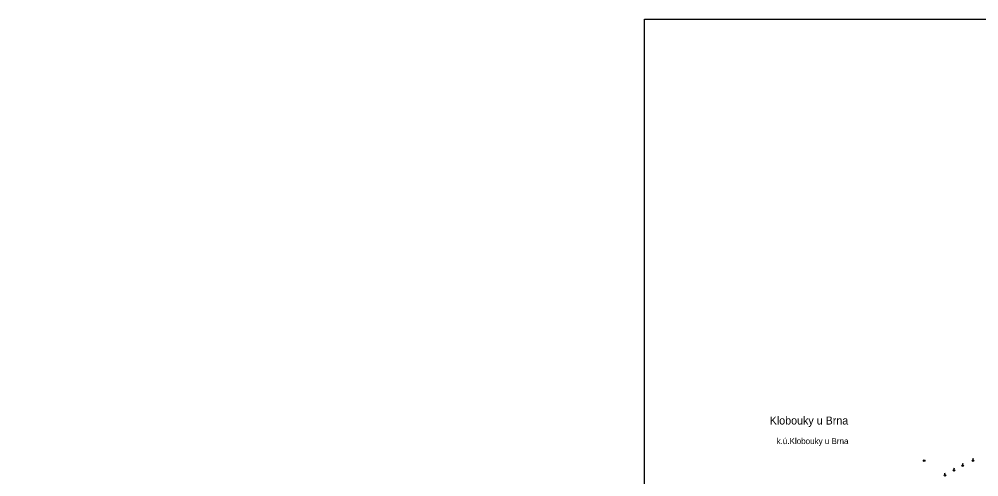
# Model space of a CAD drawing. Extents: x -582188 to -561562, y -1187250 to -1183500.
# Drawn here: x -582187.5 to -581707.9, y -1186228.8 to -1186000 of the extents above; entities that cross this region are included whole.
import ezdxf

# ---------------------------------------------------------------- set-up
doc = ezdxf.new("R2010")
doc.units = 0
for name, color, linetype in [('MAP_ZN_BP', 7, 'Continuous'), ('NÁZEV_K_Ú', 7, 'Continuous'), ('NÁZVY_SÍDEL_JEDNOTKY', 7, 'Continuous'), ('RÁMY_ML', 7, 'Continuous'), ('ZN_BP', 7, 'Continuous')]:
    doc.layers.add(name, color=color, linetype=linetype)

msp = doc.modelspace()

# ---------------------------------------------------------------- linework, layer by layer
at = {"layer": 'MAP_ZN_BP'}
for radius in [0.375, 0.0005]:
    msp.add_circle((-581735.24, -1186220.761), radius, dxfattribs=at)
at = {"layer": 'RÁMY_ML'}
msp.add_lwpolyline([(-581875, -1186000), (-581562.5, -1186000), (-581562.5, -1186250), (-581562.5, -1186500), (-581875, -1186500), (-582187.5, -1186500), (-582187.5, -1186250), (-581875, -1186250), (-581875, -1186000)], dxfattribs=at)
at = {"layer": 'ZN_BP'}
for p, q in [((-581711.095, -1186220.984), (-581710.566, -1186220.456)), ((-581710.566, -1186220.988), (-581711.095, -1186220.456)), ((-581710.83, -1186220.345), (-581710.83, -1186219.595)), ((-581720.575, -1186225.874), (-581720.046, -1186225.346)), ((-581720.046, -1186225.878), (-581720.575, -1186225.346)), ((-581720.31, -1186225.235), (-581720.31, -1186224.485)), ((-581716.245, -1186223.484), (-581715.716, -1186222.956)), ((-581715.716, -1186223.488), (-581716.245, -1186222.956)), ((-581715.98, -1186222.845), (-581715.98, -1186222.095)), ((-581725.115, -1186228.334), (-581724.586, -1186227.806)), ((-581724.586, -1186228.338), (-581725.115, -1186227.806)), ((-581724.85, -1186227.695), (-581724.85, -1186226.945))]:
    msp.add_line(p, q, dxfattribs=at)
for points in [[(-581710.955, -1186219.845), (-581710.83, -1186219.595), (-581710.705, -1186219.845)], [(-581720.435, -1186224.735), (-581720.31, -1186224.485), (-581720.185, -1186224.735)], [(-581716.105, -1186222.345), (-581715.98, -1186222.095), (-581715.855, -1186222.345)], [(-581724.975, -1186227.195), (-581724.85, -1186226.945), (-581724.725, -1186227.195)]]:
    msp.add_lwpolyline(points, dxfattribs=at)
for centre in [(-581710.83, -1186220.72), (-581720.31, -1186225.61), (-581715.98, -1186223.22), (-581724.85, -1186228.07)]:
    msp.add_circle(centre, 0.375, dxfattribs=at)

# ---------------------------------------------------------------- texts
at = {"layer": 'NÁZEV_K_Ú'}
msp.add_text('k.ú.Klobouky u Brna', height=3, dxfattribs=at).set_placement((-581808.96, -1186212.46))
at = {"layer": 'NÁZVY_SÍDEL_JEDNOTKY'}
msp.add_text('Klobouky u Brna', height=4, dxfattribs=at).set_placement((-581812.43, -1186202.67))

doc.saveas('drawing.dxf')
